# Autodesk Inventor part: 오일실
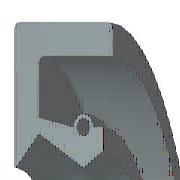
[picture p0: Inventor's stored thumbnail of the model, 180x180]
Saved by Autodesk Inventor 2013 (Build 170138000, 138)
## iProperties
Created: 2015-11
Part Number: 오일실
Material: 고무
Description: 오일-실
Document SubType Name: Modeling
Standard: KS B 2804
Designer: mdu
Standards Organization: KS
Language: ko-KR
Size Designation: D - 10 20 7
Categories: <MemberInstance><Categories><Category DisplayName="샤프트 부품" InternalName="7f7aeb1f-a693-4053-b835-cee3144e0d98" Mnemonic="SHFT"><Category DisplayName="실링" Intern
Density: 0.93 g/cm^3
Mass: 1.11329 g
Surface Area: 16.3871 cm^2
Volume: 1.19708 cm^3
IsCustomPart: 0
Author: mdu
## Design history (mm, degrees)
revolve "본체" stored, may be unused: angle "d17" = 90 deg
revolve "스프링1" stored, may be unused: angle "d18" = 90 deg
body "Solid1"
sketch "스케치1"
  geometry: L1 (0, 10)-(7, 10); L2 (7, 8.25)-(1.75, 8.25); L3 (1.75, 6.75)-(4.9, 5); L4 (4.9, 5)-(0, 5); L5 (0, 0)-(9.586, 0) reference; L6 (4.9, 5)-(6.3, 5.875); L7 (0, 18)-(0, -3) reference; L8 (-1.941, 0)-(11.507, 0) reference; L9 (4.2, 7.1)-(1.75, 7.59); L10 (1.75, 7.59)-(1.75, 8.25); L11 (0, 10)-(0, 5.088); L12 (4.9, 5)-(0, 5); L13 (1.75, 6.75)-(0.152, 5.028); L14 (7, 10)-(7, 8.25); L15 (5.6, 7.1)-(6.3, 7.1); L16 (6.3, 7.1)-(6.3, 5.875); C1 r 0.455 at (4.9, 7.1); A1 r 0.7 centre (4.9, 7.1) between (5.6, 7.1) and (4.2, 7.1); A2 r 0.088 centre (0.088, 5.088) between (0, 5.088) and (0.152, 5.028); 1 further point
  constraints: 28 end point, 5 horizontal alignment, 5 point on line, 4 point on circle, 4 vertical alignment, 3 centre point, 3 tangent, 2 collinear, 2 horizontal, 2 perpendicular, 1 coincident, 1 parallel
  dimensions: "d0" = 20 diameter of L1 L5 (= SD2); "d1" = 1.75 distance of L1.end L2.start (= SD); "d2" = 0.91 diameter of C1 (= SPDI); "d3" = 1.4 diameter of A1 (= SPDA); "d4" = 10 diameter of L3.end L5 (= NND); "d5" = 13.5 diameter of L3.start L5 (= TKDM); "d7" = 15.18 diameter of L9.end L5 (= TKDM + 0.24 x SWDT); "d8" = 1.75 distance between parallel lines of L11 L10 (= SD); "d9" = 4.9 distance from line of L11 C1.centre (= SPDST); "d10" = 14.2 diameter of C1.centre L5 (= HLDM); "d11" = 0.0875 radius of A2 (= 0.25 x LAB); "d12" = 6.3 distance between parallel lines of L11 L16 (= SDI); "d13" = 11.75 diameter of L6.end L5 (= ABDM); "d14" = 7 distance from line of L11 L1.end (= SWDT)
fillet "모깎기1" dims "d6" = 0.3 (= RR)
other parameters: "SD2" = 20 [user parameter; used in 1 equation term], "SWDT" = 7 [user parameter; used in 2 equation terms], "RR" = 0.3 [user parameter; used in 1 equation term], "SD" = 1.75 [user parameter; used in 2 equation terms], "NND" = 10 [user parameter; used in 1 equation term], "SPDA" = 1.4 [user parameter; used in 1 equation term], "SPDI" = 0.91 [user parameter; used in 1 equation term], "TKDM" = 13.5 [user parameter; used in 2 equation terms], "HLDM" = 14.2 [user parameter; used in 1 equation term], "ABDM" = 11.75 [user parameter; used in 1 equation term], "SDI" = 6.3 [user parameter; used in 1 equation term], "SPDST" = 4.9 [user parameter; used in 1 equation term], "LAB" = 0.35 [user parameter; used in 1 equation term], "d15" = 0, "d16" = 0, "d19" = 0
